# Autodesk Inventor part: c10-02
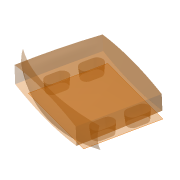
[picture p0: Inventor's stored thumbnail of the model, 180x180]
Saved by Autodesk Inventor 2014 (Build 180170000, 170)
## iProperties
Created: 2010-12
Part Number: c10-02
Material: Generic
Document SubType Name: Modeling
Designer: Thom Tremblay
Density: 1 g/cm^3
Appearance: Satin - Linen
Author: Thom Tremblay
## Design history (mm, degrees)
sketch "Sketch1"
  geometry: L1 (-60, -12)-(60, -12); L2 (60, -12)-(60, 12); L3 (60, 12)-(-60, 12); L4 (-60, 12)-(-60, -12); A1 r 350 centre (0, -332.819) between (60, 12) and (-60, 12); A2 r 350 centre (0, 332.819) between (-60, -12) and (60, -12); 3 further points
  constraints: 8 end point, 4 point on circle, 2 centre point, 2 midpoint, 2 parallel, 1 equal radius, 1 horizontal, 1 horizontal alignment, 1 perpendicular, 1 vertical alignment
  dimensions: "d0" = 120 distance of L3.end L2.end; "d1" = 24 distance of L2.end L1.end; "d2" = 350 radius of A1
workplane "Work Plane4"
sketch "Sketch5"
  geometry: L1 (-60, 12)-(-60, -12) reference; L2 (60, -12)-(60, 12) reference; L3 (-58, 10.314)-(-58, -10.314); L4 (58, -10.314)-(58, 10.314); A1 r 350 centre (0, 332.819) between (-60, -12) and (60, -12) reference; A2 r 350 centre (0, -332.819) between (60, 12) and (-60, 12) reference; A3 r 348 centre (0, 332.819) between (-58, -10.314) and (58, -10.314); A4 r 348 centre (0, -332.819) between (58, 10.314) and (-58, 10.314); 1 further point
  constraints: 4 end point, 4 point on circle, 2 centre point, 3 other
  dimensions: "d37" = 2 distance between parallel lines of L2 L4
sketch "Sketch6"
  geometry: L1 (-60, 0)-(60, 0); L2 (60, 0)-(58.843, 22.085); L3 (-60, 0)-(-58.779, 23.307); A1 r 691.758 centre (630.81, -36.204) between (-60, 0) and (-58, -100); A2 r 691.758 centre (-630.81, -36.204) between (58, -100) and (60, 0); 1 further point
  constraints: 6 end point, 4 point on circle, 2 centre point, 2 tangent, 1 horizontal
  dimensions: "d53" = 87 deg angle of L1 L3; "d54" = 87 deg angle of L1 L2 (= d53)
sketch "Sketch7"
  geometry: L1 (17.181, 0)-(12, 0) reference; L2 (15.181, -100)-(10.314, -100) reference; L3 (17.181, 0)-(16.768, 11.838); A1 r 911.322 centre (-893.585, -31.805) between (15.181, -100) and (17.181, 0); 1 further point
  constraints: 2 end point, 2 point on circle, 1 centre point, 1 tangent
  dimensions: "d56" = 88 deg angle of L1 L3
feature "LoftSrf2" sketch "Sketch5", "Sketch6", "Sketch7" dims "d57" = 0, "d58" = 90 deg, "d59" = 0, "d60" = 90 deg, "d61" = 0, "d62" = 90 deg, "d63" = 0, "d64" = 90 deg, "d65" = 0, "d66" = 90 deg
sketch "Sketch2"
  geometry: L1 (-75, -16)-(75, -16); L2 (-75, -60)-(75, -60); A1 r 183.781 centre (0, -183.781) between (75, -16) and (-75, -16); 2 further points
  constraints: 4 end point, 3 point on circle, 1 centre point, 1 coincident, 1 horizontal, 1 parallel
  dimensions: "d5" = 16 distance from line of point (0, 0) L1; "d7" = 60 distance from line of point (0, 0) L2; "d55" = 150 distance of L1.start L1.end
feature "RevolutionSrf1" sketch "Sketch2" dims angle "d8" = 40 deg
patch "Boundary Patch1" dims "d13" = 0, "d67" = 0, "d68" = 0, "d69" = 0, "d70" = 0
workplane "Work Plane1"
sketch "Sketch3"
  geometry: L1 (52, -85)-(52, -73); L2 (38, -73)-(38, -85); A1 r 7 centre (45, -73) between (52, -73) and (38, -73); A2 r 7 centre (45, -85) between (38, -85) and (52, -85); 1 further point
  constraints: 4 end point, 4 point on circle, 4 tangent, 2 centre point, 1 parallel, 1 vertical
  dimensions: "d15" = 12 distance of L1.start L1.end; "d16" = 7 radius of A1; "d50" = 45 horizontal distance of A1.centre point (0, 0); "d51" = 85 vertical distance of point (0, 0) A2.centre
extrude_surface "ExtrusionSrf2" sketch "Sketch3" dims "d19" = 14, "d20" = 5 deg
pattern_linear "Rectangular Pattern1" dims "d23" = 90
workplane "Work Plane2"
body "Srf2"
body "Srf3"
body "Srf4"
body "Srf5"
body "Srf6"
body "Srf7"
body "Srf11"
extrude_surface "ExtrusionSrf3"
extrude_surface "ExtrusionSrf4"
extrude_surface "ExtrusionSrf5"
other parameters: "d14" = -24, "d52" = -6
